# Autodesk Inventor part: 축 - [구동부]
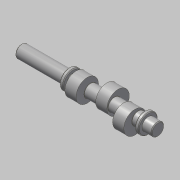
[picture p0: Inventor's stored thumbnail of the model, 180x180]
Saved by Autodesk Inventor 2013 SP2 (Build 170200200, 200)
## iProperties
Company: 한국ATC센터
Created: 2014-08
Part Number: 축 - [구동부]
Document SubType Name: Modeling
Designer: mdu
Density: 7.86 g/cm^3
Material: 강철, 연강
Mass: 516.584 g
Surface Area: 162.516 cm^2
Volume: 65.7231 cm^3
Author: mdu
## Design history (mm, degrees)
sketch "스케치1"
  geometry: L1 (-91.5, 0)-(91.5, 0); L2 (-91.5, 0)-(-91.5, 8.5); L3 (-91.5, 8.5)-(-27.5, 8.5); L4 (-27.5, 8.5)-(-27.5, 13); L5 (-27.5, 13)-(-22.5, 13); L6 (-22.5, 13)-(-22.5, 8.5); L7 (-22.5, 8.5)-(73.5, 8.5); L8 (73.5, 8.5)-(73.5, 13); L9 (73.5, 13)-(78.5, 13); L10 (78.5, 13)-(78.5, 8.5); L11 (78.5, 8.5)-(91.5, 8.5); L12 (91.5, 8.5)-(91.5, 0); 2 further points
  constraints: 24 end point, 5 parallel, 1 coincident, 1 horizontal, 1 midpoint, 1 perpendicular
  dimensions: "d0" = 183 distance of L1.start L1.end (derived); "d2" = 17 diameter of L3 L1; "d3" = 26 diameter of L5 L1; "d4" = 17 diameter of L7 L1; "d5" = 26 diameter of L9 L1; "d6" = 17 diameter of L11 L1; "d7" = 5 distance of L8.end L9.end; "d8" = 5 distance of L4.end L5.end; "d10" = 64 distance of L2.end L3.end; "d11" = 13 distance of L10.end L11.end; "d35" = 96 distance between parallel lines of L8 L6
revolve "회전1" sketch "스케치1" stored, may be unused: angle "d12" = 90 deg
node "작업 평면7"
sketch "스케치6"
  geometry: C1 r 15 at (0, 5); 1 further point
  constraints: 1 centre point, 1 vertical alignment
  dimensions: "d37" = 30 diameter of C1; "d38" = 5 distance of C1.centre point (0, 0)
extrude "돌출4" join sketch "스케치6" stored distance "d33" = 15; taper "d34" = 0 deg
node "작업 평면8"
sketch "스케치7"
  geometry: L1 (0, 0)-(-6.5, -11.258); L2 (0, 0)-(13, 0); C1 r 15 at (-2.5, -4.33); A1 r 13 centre (0, 0) between (-6.5, -11.258) and (13, 0) reference; 1 further point
  constraints: 4 end point, 2 point on circle, 1 centre point, 1 horizontal, 1 point on line
  dimensions: "d40" = 120 deg angle of L1 L2; "d41" = 30 diameter of C1; "d42" = 5 distance of point (0, 0) C1.centre
extrude "돌출5" join sketch "스케치7" stored distance "d43" = 15; taper "d44" = 0 deg
node "작업 평면9"
sketch "스케치8"
  geometry: L1 (0, 0)-(4.25, -7.361); L2 (0, 0)-(-8.5, 0); C1 r 15 at (2.5, -4.33); A1 r 8.5 centre (0, 0) between (4.25, -7.361) and (-8.5, 0) reference; 1 further point
  constraints: 4 end point, 2 point on circle, 1 centre point, 1 horizontal, 1 point on line
  dimensions: "d46" = 120 deg angle of L1 L2; "d47" = 30 diameter of C1; "d48" = 5 distance of point (0, 0) C1.centre
extrude "돌출6" join sketch "스케치8" stored distance "d49" = 15; taper "d50" = 0 deg
node "작업 평면3"
sketch "스케치5"
  geometry: L1 (32, 8.5)-(32, -8.5) reference; L2 (27.5, -2.5)-(14.5, -2.5); L3 (14.5, 2.5)-(27.5, 2.5); A1 r 2.5 centre (14.5, 0) between (14.5, 2.5) and (14.5, -2.5); A2 r 2.5 centre (27.5, 0) between (27.5, -2.5) and (27.5, 2.5); 4 further points
  constraints: 4 end point, 4 point on circle, 4 tangent, 2 centre point, 2 point on line, 1 horizontal alignment, 1 midpoint, 1 parallel, 1 perpendicular
  dimensions: "d23" = 5 distance between parallel lines of L3 L2; "d36" = 20 dimension on A1 L1; "d52" = 2 distance edge to line of A2 L1
extrude "돌출3" cut sketch "스케치5" distance "d25" = 3; taper "d26" = 0 deg
chamfer "모따기1" distance "d27" = 1; stored, may be unused: second distance "d28" = 2, angle "d29" = 45 deg
fillet "모깎기1" dims "d51" = 0.3
chamfer "모따기2" distance "d53" = 1; stored, may be unused: second distance "d54" = 2, angle "d55" = 45 deg
node "작업 평면10"
node "솔리드1"
other parameters: "d39" = -32, "d45" = 32
